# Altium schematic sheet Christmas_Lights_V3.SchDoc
size A2; SheetNumber: 1; SheetTotal: 1
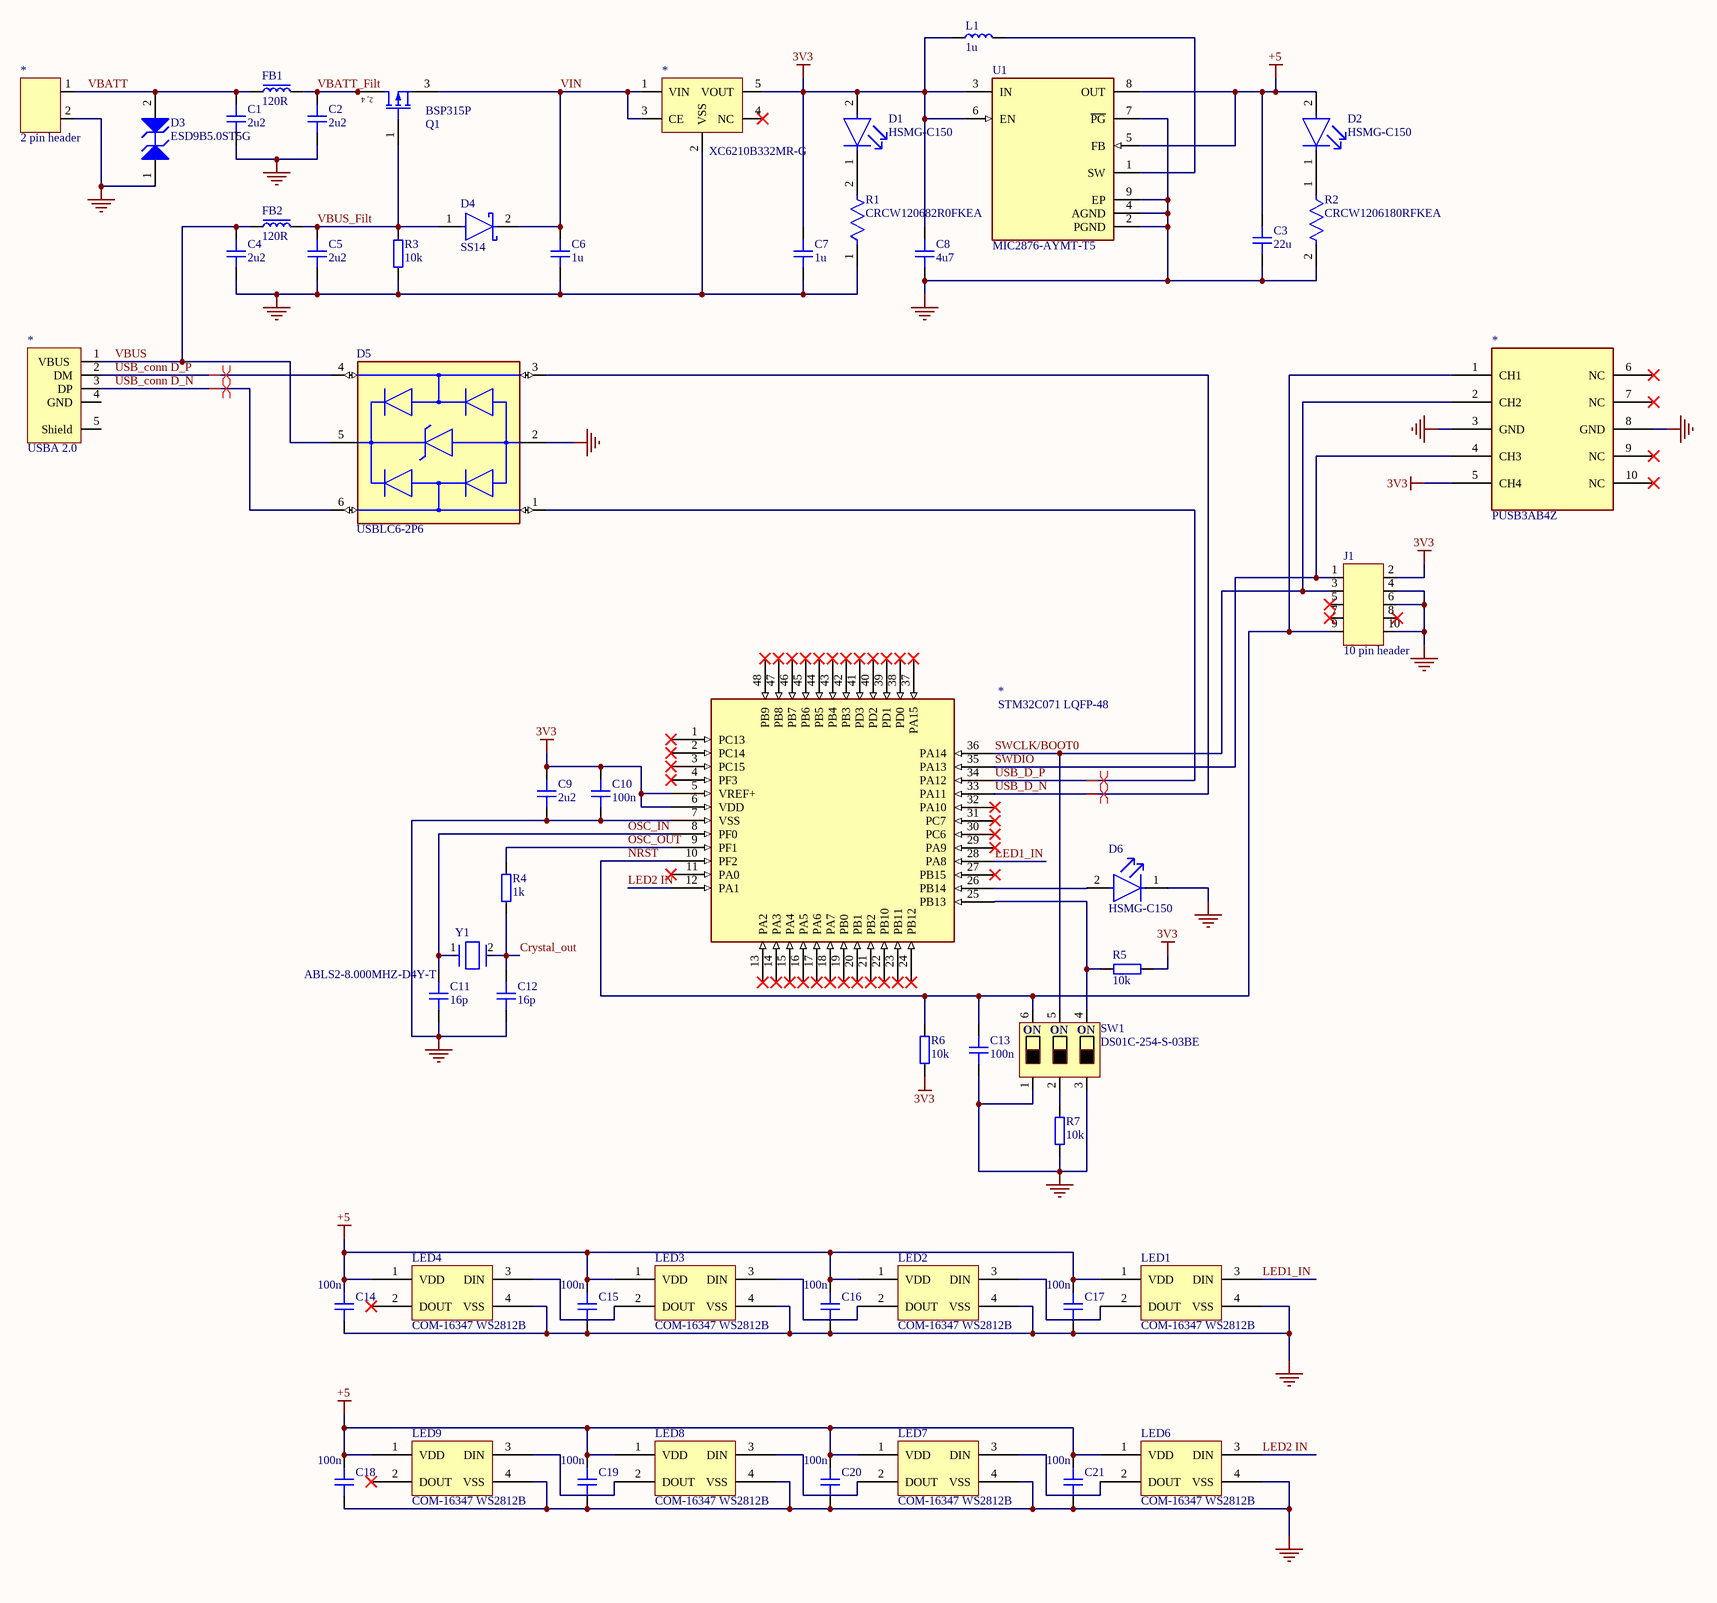
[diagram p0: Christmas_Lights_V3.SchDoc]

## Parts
(Parts that share a designator on the sheet are numbered #1, #2 ... from top to bottom, then left to right.)
*#1  2 pin header  [Screw connector]
*#2  XC6210B332MR-G  [SOT25]
*#3  USBA 2.0  [USB A 87583 2010]
*#4  PUSB3AB4Z  [SOT1176-1]
*#5  STM32C071 LQFP-48  [LQFP-48]
C1  2u2  [CAP_0603]
C2  2u2  [CAP_0603]
C3  22u  [CAP_0805]
C4  2u2  [CAP_0603]
C5  2u2  [CAP_0603]
C6  1u  [CAP_0603]
C7  1u  [CAP_0603]
C8  4u7  [CAP_0603]
C9  2u2  [CAP_0603]
C10  100n  [CAP_0603]
C11  16p  [CAP_0603]
C12  16p  [CAP_0603]
C13  100n  [CAP_0603]
C14  100n  [CAP_0603]
C15  100n  [CAP_0603]
C16  100n  [CAP_0603]
C17  100n  [CAP_0603]
C18  100n  [CAP_0603]
C19  100n  [CAP_0603]
C20  100n  [CAP_0603]
C21  100n  [CAP_0603]
D1  HSMG-C150  [FP-HSMG-C150-MFG]
D2  HSMG-C150  [FP-HSMG-C150-MFG]
D3  ESD9B5.0ST5G  [ONSC-SOD-923-2-514AB-01_V]
D4  SS14  [FP-403AE-MFG]
D5  USBLC6-2P6  [FP-SOT-666-MFG]
D6  HSMG-C150  [FP-HSMG-C150-MFG]
FB1  120R  [FB_0603]
FB2  120R  [FB_0603]
J1  10 pin header  [5x2 10 pin (1.27mm)]
L1  1u  [IND_0603]
LED1  COM-16347 WS2812B  [COM-16347]
LED2  COM-16347 WS2812B  [COM-16347]
LED3  COM-16347 WS2812B  [COM-16347]
LED4  COM-16347 WS2812B  [COM-16347]
LED6  COM-16347 WS2812B  [COM-16347]
LED7  COM-16347 WS2812B  [COM-16347]
LED8  COM-16347 WS2812B  [COM-16347]
LED9  COM-16347 WS2812B  [COM-16347]
Q1  BSP315P  [INF-PG-SOT223_SC-73_L]
R1  CRCW120682R0FKEA  [FP-CRCW1206-e3-IPC_A]
R2  CRCW1206180RFKEA  [FP-CRCW1206-e3-IPC_C]
R3  10k  [RES_0603]
R4  1k  [RES_0603]
R5  10k  [RES_0603]
R6  10k  [RES_0603]
R7  10k  [RES_0603]
SW1  DS01C-254-S-03BE  [DS01C-254-S-03BE]
U1  MIC2876-AYMT-T5  [FP-TDFN22-8LD-PL-1-MFG]
Y1  ABLS2-8.000MHZ-D4Y-T  [FP-ABLS2-MFG]

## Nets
3V3: *#2.5(VOUT) *#4.5(CH4) *#5.5(VREF+) *#5.6(VDD) C7.2 C8.2 C9.2 C10.2 D1.2(A) J1.2 L1.1 R5.2 R6.2 U1.3(IN) U1.6(EN)
+5: C3.2 C14.2 C15.2 C16.2 C17.2 C18.2 C19.2 C20.2 C21.2 D2.2(A) LED1.1(VDD) LED2.1(VDD) LED3.1(VDD) LED4.1(VDD) LED6.1(VDD) LED7.1(VDD) LED8.1(VDD) LED9.1(VDD) U1.5(FB) U1.8(OUT)
Net*#1_2: *#1.2 *#2.2(VSS) *#4.3(GND) *#4.8(GND) *#5.7(VSS) C1.1 C2.1 C3.1 C4.1 C5.1 C6.1 C7.1 C8.1 C9.1 C10.1 C11.1 C12.1 C13.1 C14.1 C15.1 C16.1 C17.1 C18.1 C19.1 C20.1 C21.1 D3.1(A1) D5.2(GND) D6.1(C) J1.4 J1.6 J1.10 LED1.4(VSS) LED2.4(VSS) LED3.4(VSS) LED4.4(VSS) LED6.4(VSS) LED7.4(VSS) LED8.4(VSS) LED9.4(VSS) R1.1 R2.2 R3.1 R7.2 SW1.1 SW1.3 U1.2(PGND) U1.4(AGND) U1.7(~{PG}) U1.9(EP)
Crystal_out: C12.2 R4.2 Y1.2
LED1_IN: *#5.28(PA8) LED1.3(DIN)
LED2 IN: *#5.12(PA1) LED6.3(DIN)
NRST: *#4.1(CH1) *#5.10(PF2) C13.2 J1.9 R6.1 SW1.6
OSC_IN: *#5.8(PF0) C11.2 Y1.1
OSC_OUT: *#5.9(PF1) R4.1
SWCLK/BOOT0: *#4.2(CH2) *#5.36(PA14) J1.3 SW1.5
SWDIO: *#4.4(CH3) *#5.35(PA13) J1.1
USB_conn D_N: *#3.3(DP) D5.6(I/O1)
USB_conn D_P: *#3.2(DM) D5.4(I/O2)
USB_D_N: *#5.33(PA11) D5.3(I/O2)
USB_D_P: *#5.34(PA12) D5.1(I/O1)
VBATT: *#1.1 C1.2 D3.2(A2) FB1.1
VBATT_Filt: C2.2 FB1.2 Q1.2(D) Q1.4(D)
VBUS: *#3.1(VBUS) C4.2 D5.5(VBUS) FB2.1
VBUS_Filt: C5.2 D4.1(A) FB2.2 Q1.1(G) R3.2
VIN: *#2.1(VIN) *#2.3(CE) C6.2 D4.2(C) Q1.3(S)
Net*#5_25: *#5.25(PB13) R5.1 SW1.4
Net*#5_26: *#5.26(PB14) D6.2(A)
NetD1_1: D1.1(C) R1.2
NetD2_1: D2.1(C) R2.1
NetL1_2: L1.2 U1.1(SW)
NetLED1_2: LED1.2(DOUT) LED2.3(DIN)
NetLED2_2: LED2.2(DOUT) LED3.3(DIN)
NetLED3_2: LED3.2(DOUT) LED4.3(DIN)
NetLED6_2: LED6.2(DOUT) LED7.3(DIN)
NetLED7_2: LED7.2(DOUT) LED8.3(DIN)
NetLED8_2: LED8.2(DOUT) LED9.3(DIN)
NetR7_1: R7.1 SW1.2

Not connected (* = marked no-connect by the designer): *#2 4(NC)*; *#3 4(GND) 5(Shield); *#4 6(NC)* 7(NC)* 9(NC)* 10(NC)*; *#5 1(PC13)* 2(PC14)* 3(PC15)* 4(PF3)* 11(PA0)* 13(PA2)* 14(PA3)* 15(PA4)* 16(PA5)* 17(PA6)* 18(PA7)* 19(PB0)* 20(PB1)* 21(PB2)* 22(PB10)* 23(PB11)* 24(PB12)* 27(PB15)* 29(PA9)* 30(PC6)* 31(PC7)* 32(PA10)* 37(PA15)* 38(PD0)* 39(PD1)* 40(PD2)* 41(PD3)* 42(PB3)* 43(PB4)* 44(PB5)* 45(PB6)* 46(PB7)* 47(PB8)* 48(PB9)*; J1 5* 7* 8*; LED4 2(DOUT)*; LED9 2(DOUT)*

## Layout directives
differential pair: USB_conn D_N, USB_conn D_P, USB_D_N, USB_D_P

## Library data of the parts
C1 C2 C4-C21 = CAP_0603: Capacitor SMD 0603
C3 = CAP_0805: Capacitor SMD 0805
D1 D2 D6 = CMP-2000-05061-2: LED GREEN DIFFUSED 1206 SMD; Manufacturer: Broadcom; Led Orientation: Top View; Max Junction Temp: +95°C; Peak Emmision Wavelength: 570nm; Viewing Angle: 170°; Wavelength: 572nm; Reverse Voltage: 5V; Luminous Intensity: 15mcd; Forward Voltage: 2.2V; Power Dissipation: 65mW; Forward Current: 20mA
D3 = CMP-1063-00119-1: Transient Voltage Suppressor, Micro-Packaged Diode for ESD Protection, 2-Pin SOD-923, Pb-Free, Tape and Reel; Manufacturer: On Semiconductor; Number of Lines: 1; Direction: Bidirectional; V(BR) Min (V): 5.8; VRWM Max (V): 5
D4 = CMP-2000-04943-2: DIODE SCHOTTKY 40V 1A SMA; Manufacturer: ON Semiconductor; Peak Reverse Current: 0.2mA; Max Junction Temp: +125°C; Standoff Height: 0.05mm; Max Surge Forward Current: 40A
D5 = CMP-12225-000058-1: TVS DIODE 5.25V 17V SOT666; Min Breakdown Voltage: 6V; Power Line Protection: Yes; Element Configuration: Dual; Test Current: 1mA; Working Voltage: 5V; Number of Channels: 2; Max Reverse Leakage Current: 150nA; Direction: Unidirectional; Peak Pulse Current: 5A; Number of Elements: 1; Capacitance: 3.5pF
FB1 FB2 = FB_0603: Ferrite Bead SMD 0603
L1 = IND_0603: Inductor SMD 0603
Q1 = CMP-1099-00022-1: P-Channel SIPMOS Small-Signal-Transistor, -60 V VDS, -1.17 A ID, -55 to 150 degC, PG-SOT223 (SC-73), Reel, Green; Manufacturer: Infineon; ID (max): -1.17Â A; Polarity: P; VGS(th) (min): -1Â V; IDpuls (max): -4.68Â A; Pto t (max): 1.8Â W; QG: -5.2Â nC; Rth: 115Â K/W; Mode: Enhancement; Green: TRUE; RDS (on) (max): 800Â mOhm; VGS(th) (max): -2Â V; VDS (max): -60Â V
R1 = CMP-2003-02405-2: RES Thick Film, 82Ω, 1%, 0.25W, 100ppm/°C, 1206; Resistance: 82R; Max Power Dissipation: 250mW; Working Voltage: 200V
R2 = CMP-2003-01848-2: RES Thick Film, 180Ω, 1%, 0.25W, 100ppm/°C, 1206; Voltage Rating (DC): 200V; Resistance: 180R; Power Rating: 250mW
R3-R7 = RES_0603: Resistor SMD 0603
SW1 = DS01C-254-S-03BE: DIP Switch SPST 3 Positions Short Pins 2.54mm Pitch; Manufacturer: CUI Devices
U1 = CMP-06325-000017-1: IC REG BOOST ADJ 3.8A 8TDFN; Output Type: Adjustable; Max Input Voltage: 5.5V; Synchronous Rectifier: No; Number of Outputs: 1; Min Input Voltage: 2.5V; Switching Frequency: 2MHz; Output Configuration: Positive
Y1 = CMP-27762-001729-1: CRYSTAL 8.0000MHZ 18PF SMD; Series Resistance: 80R; Tolerance: 30ppm; Frequency: 8MHz; Operating Frequency: 8 MHz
